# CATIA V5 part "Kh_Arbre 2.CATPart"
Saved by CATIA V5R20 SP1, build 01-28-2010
Part number: Arbre 2
Bounding box of the stored display mesh (mm): x -110 to 84, y -15 to 15, z -15 to 15
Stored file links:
  G:\Khaled_CFAO_2011\SIL\SIL_GR1\tmerino\Khaled\CAD_Thinkmotion\Kh_Arbre 2.CATPart
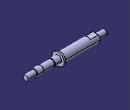
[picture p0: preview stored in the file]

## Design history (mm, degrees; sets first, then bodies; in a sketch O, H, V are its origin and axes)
Body1 (main body)
  Sketch1 on yz-plane, origin (0, 0, 0), H (0, 1, 0), V (0, 0, 1)
    circle A1 centre (0, 0) radius 15
    radius A1 = 15
  Pad1: profile Sketch1, direction (1, 0, 0), length 4
  Sketch2 on end face of Pad1, origin (4, 0, 0), H (0, 1, 0), V (0, 0, 1)
  Sketch3 on start face of Pad1, origin (0, 0, 0), H (0, -1, 0), V (0, 0, 1)
    circle A1 centre (0, 0) radius 11
    radius A1 = 11
  Pad2: profile Sketch3, direction (-1, 0, 0), length 88
  Sketch4 on end face of Pad2, origin (-88, 0, 0), H (0, -1, 0), V (0, 0, 1)
    circle A1 centre (0, 0) radius 6
    radius A1 = 6
  Pad3: profile Sketch4, direction (-1, 0, 0), length 22
  Sketch5 on zx-plane, origin (0, 0, 0), H (-1, 0, 0), V (0, 0, 1)
    line L1 (68, 20) -> (88, 20)
    line L2 (88, 20) -> (88, 8.5)
    line L3 (88, 8.5) -> (68, 8.5)
    line L4 (68, 8.5) -> (68, 20)
    reference projected line E1 (88, 11) -> (88, -11) from edge [face of Pad2 from Sketch3.A1 | end face of Pad2]
    reference projected line E2 through (0, 0) direction (1, 0) from axis of face of Pad2 from Sketch3.A1
    distance E1 L2 = 0
    distance L2 L4 = 20
    distance E2 L3 = 8.5
    horizontal: L1 H, L3 H
    vertical: L2 V, L4 V
  Pocket1: profile Sketch5, direction (0, 1, 0), length 22, opposite side length 22
  Sketch6 on end face of Pad1, origin (4, 0, 0), H (0, 1, 0), V (0, 0, 1)
    circle A1 centre (0, 0) radius 8.5
    radius A1 = 8.5
  Pad4: profile Sketch6, direction (1, 0, 0), length 16
  Sketch7 on end face of Pad4, origin (20, 0, 0), H (0, 1, 0), V (0, 0, 1)
    circle A1 centre (0, 0) radius 7.5
    radius A1 = 7.5
  Pad5: profile Sketch7, direction (1, 0, 0), length 26
  Sketch8 on end face of Pad5, origin (46, 0, 0), H (0, 1, 0), V (0, 0, 1)
    circle A1 centre (0, 0) radius 8.5
    radius A1 = 8.5
  Pad6: profile Sketch8, direction (1, 0, 0), length 16
  Sketch9 on end face of Pad6, origin (62, 0, 0), H (0, 1, 0), V (0, 0, 1)
    circle A1 centre (0, 0) radius 6
    radius A1 = 6
  Pad7: profile Sketch9, direction (1, 0, 0), length 22
  Chamfer1: length 1, angle 45, on edge [face of Pad4 from Sketch6.A1 | end face of Pad4]
  Chamfer2: length 1, angle 45, on edge [start face of Pad6 | face of Pad6 from Sketch8.A1]
  Fillet1: radius 2, on edge [start face of Pad1 | face of Pad2 from Sketch3.A1]
  Thread1: diameter 12, depth 10, pitch 1, on face of Pad3 from Sketch4.A1, from end face of Pad2
  Thread2: diameter 12, depth 10, pitch 1, on face of Pad7 from Sketch9.A1, from end face of Pad6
